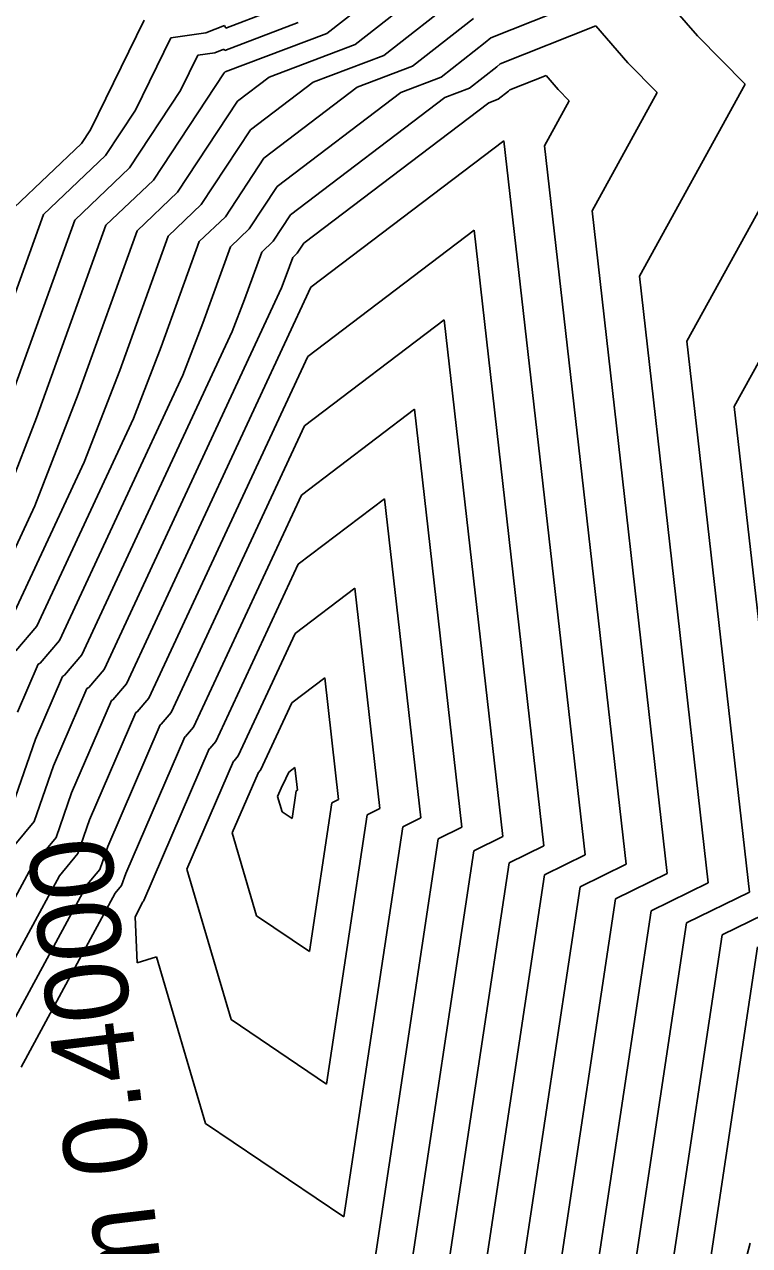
# Model space of a CAD drawing. Extents: x -549394 to -546608, y -1037055 to -1033629.
# Drawn here: x -547677.3 to -547598.3, y -1035584.6 to -1035451.6 of the extents above; entities that cross this region are included whole.
import ezdxf

# ---------------------------------------------------------------- set-up
doc = ezdxf.new("R2010")
doc.units = 0
for name, color, linetype in [('hlavni_vrst', 7, 'Continuous'), ('norm_vrst', 7, 'Continuous'), ('x_popis_pricne_rezy_C1', 7, 'Continuous')]:
    doc.layers.add(name, color=color, linetype=linetype)

msp = doc.modelspace()

# ---------------------------------------------------------------- linework, layer by layer
at = {"layer": 'hlavni_vrst'}
for p, q in [((-547629.64, -1035448.26), (-547638.14, -1035454.93)), ((-547664.28, -1035451.11), (-547670.13, -1035463.03)), ((-547638.14, -1035454.93), (-547645.86, -1035457.85)), ((-547599.94, -1035493.2), (-547579.61, -1035456.26)), ((-547645.86, -1035457.85), (-547652.67, -1035463.03)), ((-547670.13, -1035463.03), (-547671.12, -1035464.52)), ((-547652.67, -1035463.03), (-547658.05, -1035471.18)), ((-547671.12, -1035464.52), (-547678.47, -1035471.52)), ((-547625.05, -1035464.23), (-547646.1, -1035480.2)), ((-547616.21, -1035542.07), (-547625.05, -1035464.23)), ((-547658.05, -1035471.18), (-547661.66, -1035474.62)), ((-547661.66, -1035474.62), (-547666.95, -1035489.27)), ((-547646.1, -1035480.2), (-547666.22, -1035523.41)), ((-547666.95, -1035489.27), (-547670.82, -1035499.26)), ((-547593.82, -1035547.12), (-547599.94, -1035493.2)), ((-547670.82, -1035499.26), (-547678.41, -1035515.56)), ((-547641.33, -1035513.01), (-547647.82, -1035517.94)), ((-547638.6, -1035537.02), (-547641.33, -1035513.01)), ((-547647.82, -1035517.94), (-547654.03, -1035531.27)), ((-547666.22, -1035523.41), (-547667.69, -1035525.15)), ((-547667.85, -1035525.24), (-547672.2, -1035535.3)), ((-547667.69, -1035525.15), (-547667.85, -1035525.24)), ((-547654.03, -1035531.27), (-547654.48, -1035531.8)), ((-547654.53, -1035531.83), (-547659.62, -1035543.61)), ((-547654.48, -1035531.8), (-547654.53, -1035531.83)), ((-547672.2, -1035535.3), (-547673.88, -1035540.16)), ((-547644.39, -1035567.05), (-547639.96, -1035537.69)), ((-547639.96, -1035537.69), (-547638.6, -1035537.02)), ((-547673.88, -1035540.16), (-547676.56, -1035543.39)), ((-547620.62, -1035544.22), (-547616.21, -1035542.07)), ((-547676.56, -1035543.39), (-547681.58, -1035552.67)), ((-547659.62, -1035543.61), (-547654.8, -1035560.01)), ((-547628.56, -1035596.95), (-547620.62, -1035544.22)), ((-547601.27, -1035550.76), (-547593.82, -1035547.12)), ((-547606.88, -1035587.96), (-547601.27, -1035550.76)), ((-547654.8, -1035560.01), (-547644.39, -1035567.05))]:
    msp.add_line(p, q, dxfattribs=at)
at = {"layer": 'norm_vrst'}
for p, q in [((-547632.18, -1035442.98), (-547644.37, -1035452.54)), ((-547630.91, -1035445.62), (-547641.26, -1035453.73)), ((-547609.59, -1035446.3), (-547626.5, -1035453)), ((-547603.97, -1035452.8), (-547609.59, -1035446.3)), ((-547650.6, -1035450.15), (-547655.37, -1035451.96)), ((-547655.53, -1035451.67), (-547657.56, -1035452.49)), ((-547655.37, -1035451.96), (-547655.53, -1035451.67)), ((-547647.49, -1035451.35), (-547655.5, -1035454.38)), ((-547628.37, -1035450.9), (-547635.03, -1035456.12)), ((-547615.02, -1035451.72), (-547625.46, -1035455.85)), ((-547611.56, -1035455.73), (-547615.02, -1035451.72)), ((-547661.36, -1035453), (-547665.23, -1035460.9)), ((-547657.56, -1035452.49), (-547661.36, -1035453)), ((-547644.37, -1035452.54), (-547655.44, -1035456.73)), ((-547626.5, -1035453), (-547627.1, -1035453.54)), ((-547598.77, -1035458.07), (-547603.97, -1035452.8)), ((-547655.58, -1035454.24), (-547656.58, -1035454.64)), ((-547655.5, -1035454.38), (-547655.58, -1035454.24)), ((-547641.26, -1035453.73), (-547650.65, -1035457.29)), ((-547627.1, -1035453.54), (-547631.91, -1035457.32)), ((-547658.44, -1035454.9), (-547660.33, -1035458.76)), ((-547656.58, -1035454.64), (-547658.44, -1035454.9)), ((-547608.35, -1035458.97), (-547611.56, -1035455.73)), ((-547655.57, -1035456.83), (-547663.27, -1035468.52)), ((-547655.44, -1035456.73), (-547655.57, -1035456.83)), ((-547635.03, -1035456.12), (-547641.07, -1035458.41)), ((-547625.83, -1035456.18), (-547628.8, -1035458.51)), ((-547625.46, -1035455.85), (-547625.83, -1035456.18)), ((-547650.65, -1035457.29), (-547654.12, -1035459.93)), ((-547641.07, -1035458.41), (-547651.22, -1035466.12)), ((-547631.91, -1035457.32), (-547636.28, -1035458.97)), ((-547620.46, -1035457.13), (-547624.42, -1035458.69)), ((-547619.15, -1035458.65), (-547620.46, -1035457.13)), ((-547610.28, -1035478.99), (-547598.77, -1035458.07)), ((-547605.11, -1035486.09), (-547589.19, -1035457.17)), ((-547660.33, -1035458.76), (-547665.89, -1035467.19)), ((-547636.28, -1035458.97), (-547649.77, -1035469.22)), ((-547631.49, -1035459.53), (-547648.32, -1035472.31)), ((-547628.8, -1035458.51), (-547631.49, -1035459.53)), ((-547625.68, -1035459.7), (-547626.7, -1035460.09)), ((-547624.56, -1035458.82), (-547625.68, -1035459.7)), ((-547624.42, -1035458.69), (-547624.56, -1035458.82)), ((-547617.94, -1035459.88), (-547619.15, -1035458.65)), ((-547615.45, -1035471.88), (-547608.35, -1035458.97)), ((-547665.23, -1035460.9), (-547668.5, -1035465.85)), ((-547654.12, -1035459.93), (-547660.66, -1035469.85)), ((-547626.7, -1035460.09), (-547646.87, -1035475.41)), ((-547620.63, -1035464.77), (-547617.94, -1035459.88)), ((-547611.73, -1035543.08), (-547620.63, -1035464.77)), ((-547668.5, -1035465.85), (-547675.25, -1035472.28)), ((-547651.22, -1035466.12), (-547655.43, -1035472.51)), ((-547665.89, -1035467.19), (-547671.85, -1035472.87)), ((-547663.27, -1035468.52), (-547668.45, -1035473.45)), ((-547660.66, -1035469.85), (-547665.06, -1035474.04)), ((-547649.77, -1035469.22), (-547652.82, -1035473.84)), ((-547675.25, -1035472.28), (-547685.11, -1035499.6)), ((-547671.85, -1035472.87), (-547680.57, -1035497.02)), ((-547655.43, -1035472.51), (-547658.27, -1035475.21)), ((-547648.32, -1035472.31), (-547650.2, -1035475.17)), ((-547607.25, -1035544.09), (-547615.45, -1035471.88)), ((-547668.45, -1035473.45), (-547676.03, -1035494.44)), ((-547665.06, -1035474.04), (-547671.49, -1035491.85)), ((-547652.82, -1035473.84), (-547654.87, -1035475.8)), ((-547628.31, -1035473.99), (-547646.45, -1035487.75)), ((-547620.69, -1035541.06), (-547628.31, -1035473.99)), ((-547658.27, -1035475.21), (-547662.41, -1035486.68)), ((-547650.2, -1035475.17), (-547651.47, -1035476.38)), ((-547646.87, -1035475.41), (-547647.59, -1035476.5)), ((-547654.87, -1035475.8), (-547657.87, -1035484.1)), ((-547651.47, -1035476.38), (-547653.33, -1035481.52)), ((-547648.08, -1035476.97), (-547648.79, -1035478.93)), ((-547647.59, -1035476.5), (-547648.08, -1035476.97)), ((-547648.79, -1035478.93), (-547649.31, -1035480.27)), ((-547602.78, -1035545.1), (-547610.28, -1035478.99)), ((-547649.31, -1035480.27), (-547668.66, -1035521.84)), ((-547653.33, -1035481.52), (-547654.68, -1035485.02)), ((-547654.68, -1035485.02), (-547671.09, -1035520.27)), ((-547657.87, -1035484.1), (-547660.06, -1035489.77)), ((-547631.56, -1035483.75), (-547646.79, -1035495.29)), ((-547625.17, -1035540.05), (-547631.56, -1035483.75)), ((-547598.3, -1035546.11), (-547605.11, -1035486.09)), ((-547662.41, -1035486.68), (-547665.44, -1035494.51)), ((-547646.45, -1035487.75), (-547663.78, -1035524.99)), ((-547660.06, -1035489.77), (-547673.53, -1035518.7)), ((-547671.49, -1035491.85), (-547676.2, -1035504.01)), ((-547634.82, -1035493.5), (-547647.13, -1035502.84)), ((-547629.65, -1035539.04), (-547634.82, -1035493.5)), ((-547676.03, -1035494.44), (-547681.58, -1035508.76)), ((-547665.44, -1035494.51), (-547675.97, -1035517.13)), ((-547646.79, -1035495.29), (-547661.34, -1035526.56)), ((-547647.13, -1035502.84), (-547658.9, -1035528.13)), ((-547638.07, -1035503.26), (-547647.48, -1035510.39)), ((-547634.12, -1035538.03), (-547638.07, -1035503.26)), ((-547676.2, -1035504.01), (-547680.85, -1035513.99)), ((-547647.48, -1035510.39), (-547656.47, -1035529.7)), ((-547675.97, -1035517.13), (-547678.26, -1035519.83)), ((-547673.53, -1035518.7), (-547675.62, -1035521.16)), ((-547671.09, -1035520.27), (-547672.97, -1035522.49)), ((-547675.84, -1035521.29), (-547678.1, -1035526.5)), ((-547675.62, -1035521.16), (-547675.84, -1035521.29)), ((-547668.66, -1035521.84), (-547670.33, -1035523.82)), ((-547673.18, -1035522.61), (-547676.13, -1035529.43)), ((-547672.97, -1035522.49), (-547673.18, -1035522.61)), ((-547644.59, -1035522.77), (-547648.17, -1035525.49)), ((-547643.08, -1035536.01), (-547644.59, -1035522.77)), ((-547670.52, -1035523.92), (-547674.16, -1035532.36)), ((-547670.33, -1035523.82), (-547670.52, -1035523.92)), ((-547663.78, -1035524.99), (-547665.05, -1035526.48)), ((-547648.17, -1035525.49), (-547651.59, -1035532.84)), ((-547665.19, -1035526.56), (-547670.23, -1035538.23)), ((-547665.05, -1035526.48), (-547665.19, -1035526.56)), ((-547661.34, -1035526.56), (-547662.41, -1035527.81)), ((-547662.52, -1035527.88), (-547668.26, -1035541.16)), ((-547662.41, -1035527.81), (-547662.52, -1035527.88)), ((-547658.9, -1035528.13), (-547659.76, -1035529.14)), ((-547676.13, -1035529.43), (-547678.64, -1035536.68)), ((-547659.86, -1035529.19), (-547666.29, -1035544.09)), ((-547659.76, -1035529.14), (-547659.86, -1035529.19)), ((-547656.47, -1035529.7), (-547657.12, -1035530.47)), ((-547657.2, -1035530.51), (-547664.33, -1035547.03)), ((-547657.12, -1035530.47), (-547657.2, -1035530.51)), ((-547674.16, -1035532.36), (-547676.26, -1035538.42)), ((-547651.59, -1035532.84), (-547651.84, -1035533.13)), ((-547647.84, -1035532.53), (-547648.51, -1035533.03)), ((-547647.56, -1035535), (-547647.84, -1035532.53)), ((-547651.87, -1035533.15), (-547654.67, -1035539.65)), ((-547651.84, -1035533.13), (-547651.87, -1035533.15)), ((-547648.51, -1035533.03), (-547649.15, -1035534.41)), ((-547649.2, -1035534.47), (-547649.73, -1035535.68)), ((-547649.15, -1035534.41), (-547649.2, -1035534.46)), ((-547649.2, -1035534.46), (-547649.2, -1035534.47)), ((-547648.16, -1035538.1), (-547647.7, -1035535.07)), ((-547647.7, -1035535.07), (-547647.56, -1035535)), ((-547649.73, -1035535.68), (-547649.23, -1035537.37)), ((-547646.27, -1035552.57), (-547643.83, -1035536.38)), ((-547643.83, -1035536.38), (-547643.08, -1035536.01)), ((-547670.23, -1035538.23), (-547671.5, -1035541.9)), ((-547649.23, -1035537.37), (-547648.16, -1035538.1)), ((-547636.09, -1035538.99), (-547634.12, -1035538.03)), ((-547676.26, -1035538.42), (-547679.6, -1035542.44)), ((-547642.5, -1035581.52), (-547636.09, -1035538.99)), ((-547632.22, -1035540.3), (-547629.65, -1035539.04)), ((-547654.67, -1035539.65), (-547652.02, -1035548.69)), ((-547640.62, -1035596), (-547632.22, -1035540.3)), ((-547628.35, -1035541.61), (-547625.17, -1035540.05)), ((-547671.5, -1035541.9), (-547673.53, -1035544.33)), ((-547668.26, -1035541.16), (-547669.12, -1035543.64)), ((-547637.23, -1035600.54), (-547628.35, -1035541.61)), ((-547624.49, -1035542.91), (-547620.69, -1035541.06)), ((-547632.9, -1035598.75), (-547624.49, -1035542.91)), ((-547616.75, -1035545.53), (-547611.73, -1035543.08)), ((-547673.53, -1035544.33), (-547680.29, -1035556.85)), ((-547669.12, -1035543.64), (-547670.49, -1035545.28)), ((-547666.29, -1035544.09), (-547666.74, -1035545.38)), ((-547612.88, -1035546.84), (-547607.25, -1035544.09)), ((-547670.49, -1035545.28), (-547678.99, -1035561.02)), ((-547667.45, -1035546.23), (-547677.7, -1035565.2)), ((-547666.74, -1035545.38), (-547667.45, -1035546.23)), ((-547624.22, -1035595.15), (-547616.75, -1035545.53)), ((-547609.01, -1035548.14), (-547602.78, -1035545.1)), ((-547605.14, -1035549.45), (-547598.3, -1035546.11)), ((-547664.41, -1035547.18), (-547665.28, -1035548.8)), ((-547664.36, -1035547.12), (-547664.41, -1035547.18)), ((-547664.33, -1035547.03), (-547664.36, -1035547.12)), ((-547619.89, -1035593.35), (-547612.88, -1035546.84)), ((-547665.28, -1035548.8), (-547665.06, -1035553.81)), ((-547652.02, -1035548.69), (-547646.27, -1035552.57)), ((-547615.55, -1035591.55), (-547609.01, -1035548.14)), ((-547611.21, -1035589.76), (-547605.14, -1035549.45)), ((-547602.54, -1035586.16), (-547597.4, -1035552.07)), ((-547665.06, -1035553.81), (-547662.92, -1035553.17)), ((-547662.92, -1035553.17), (-547657.59, -1035571.33)), ((-547657.59, -1035571.33), (-547642.5, -1035581.52)), ((-547600.74, -1035593.87), (-547598.2, -1035584.36))]:
    msp.add_line(p, q, dxfattribs=at)

# ---------------------------------------------------------------- texts
at = {"layer": 'x_popis_pricne_rezy_C1'}
msp.add_text('PŘ 5 km 0.4000', height=9.0627, rotation=96.8244, dxfattribs=at).set_placement((-547657.74, -1035626.02))

doc.saveas('drawing.dxf')
